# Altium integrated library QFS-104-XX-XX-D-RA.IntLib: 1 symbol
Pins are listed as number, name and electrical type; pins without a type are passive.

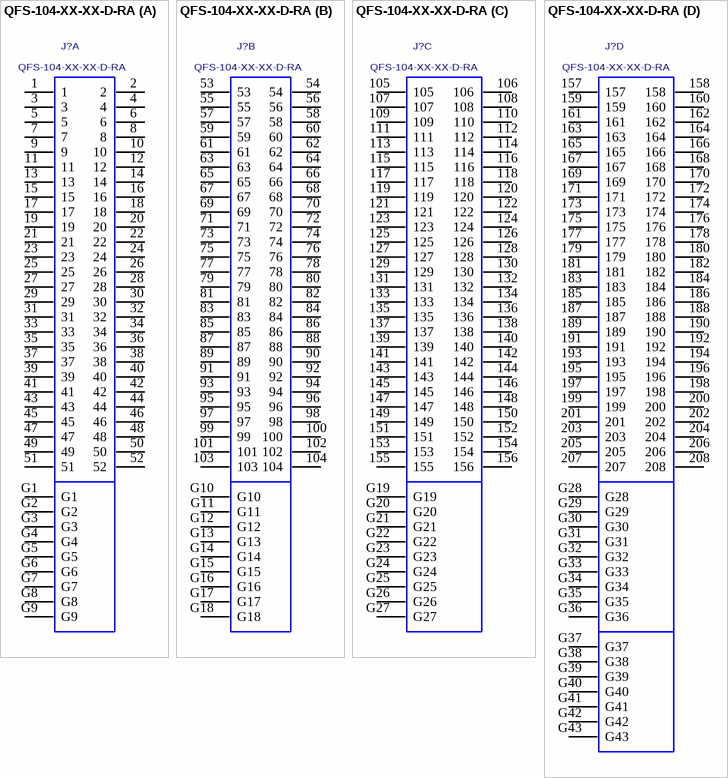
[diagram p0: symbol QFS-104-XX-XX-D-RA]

## QFS-104-XX-XX-D-RA
designator J?
0.635MM DUAL ROW RIGHT ANGLE SOCKET ASSEMBLY; MANUFACTURER: SAMTEC
footprint QFS-104-XX-XX-D-RA
part A pins: 1, 2, 3, 4, 5, 6, 7, 8, 9, 10, 11, 12, 13, 14, 15, 16, 17, 18, 19, 20, 21, 22, 23, 24, 25, 26, 27, 28, 29, 30, 31, 32, 33, 34, 35, 36, 37, 38, 39, 40, 41, 42, 43, 44, 45, 46, 47, 48, 49, 50, 51, 52, G1, G2, G3, G4, G5, G6, G7, G8, G9
part B pins: 53, 54, 55, 56, 57, 58, 59, 60, 61, 62, 63, 64, 65, 66, 67, 68, 69, 70, 71, 72, 73, 74, 75, 76, 77, 78, 79, 80, 81, 82, 83, 84, 85, 86, 87, 88, 89, 90, 91, 92, 93, 94, 95, 96, 97, 98, 99, 100, 101, 102, 103, 104, G10, G11, G12, G13, G14, G15, G16, G17, G18
part C pins: 105, 106, 107, 108, 109, 110, 111, 112, 113, 114, 115, 116, 117, 118, 119, 120, 121, 122, 123, 124, 125, 126, 127, 128, 129, 130, 131, 132, 133, 134, 135, 136, 137, 138, 139, 140, 141, 142, 143, 144, 145, 146, 147, 148, 149, 150, 151, 152, 153, 154, 155, 156, G19, G20, G21, G22, G23, G24, G25, G26, G27
part D pins: 157, 158, 159, 160, 161, 162, 163, 164, 165, 166, 167, 168, 169, 170, 171, 172, 173, 174, 175, 176, 177, 178, 179, 180, 181, 182, 183, 184, 185, 186, 187, 188, 189, 190, 191, 192, 193, 194, 195, 196, 197, 198, 199, 200, 201, 202, 203, 204, 205, 206, 207, 208, G28, G29, G30, G31, G32, G33, G34, G35, G36, G37, G38, G39, G40, G41, G42, G43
